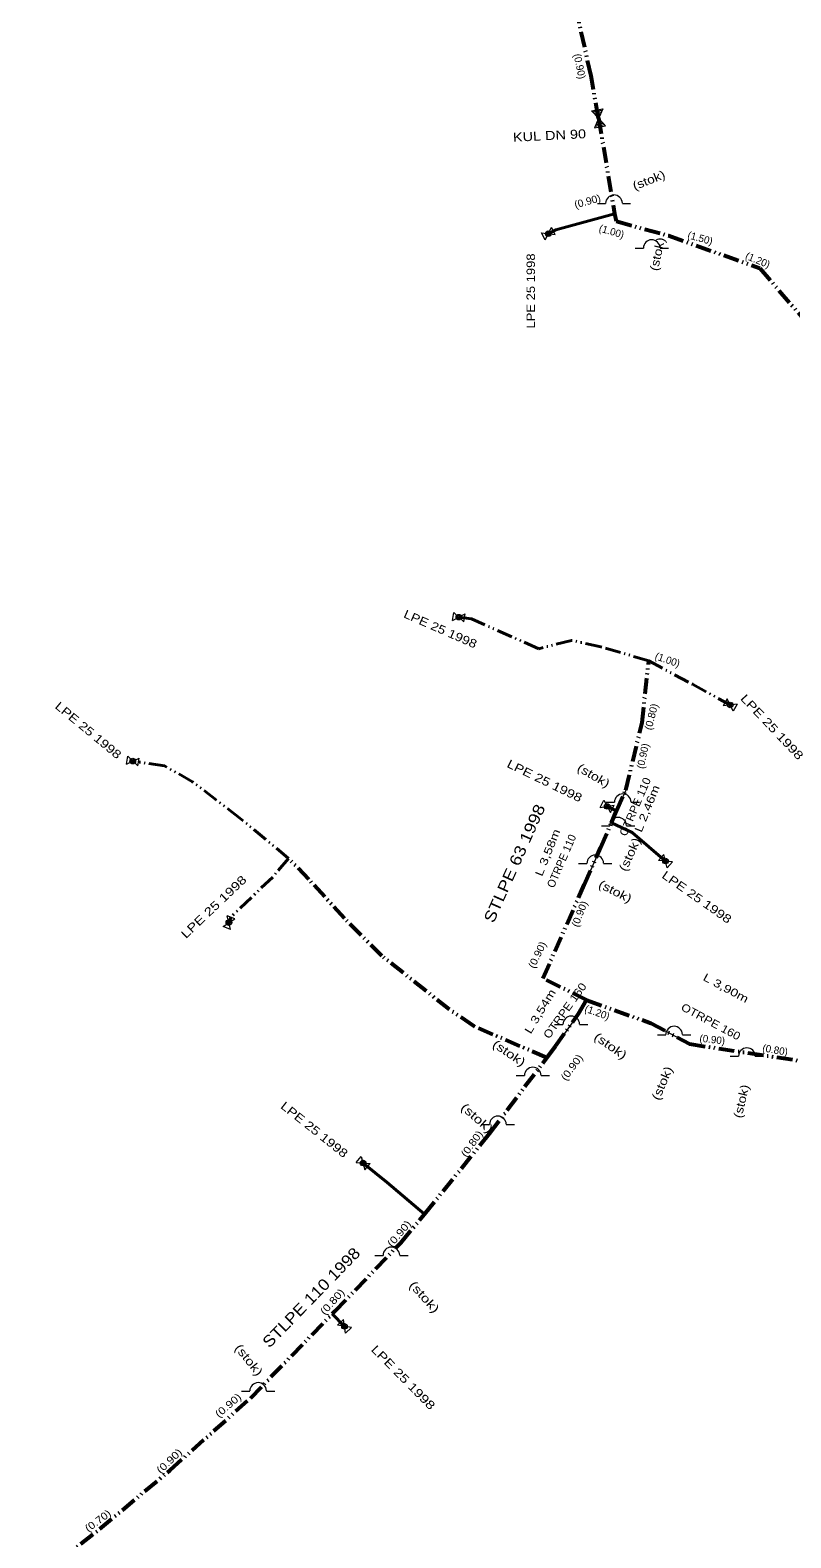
# Model space of a CAD drawing. Extents: x -648036 to -642998, y -1161549 to -1158141.
# Drawn here: x -644468.6 to -644401.1, y -1160280.5 to -1160146.5 of the extents above; entities that cross this region are included whole.
import ezdxf
from ezdxf.enums import TextEntityAlignment as Align

# ---------------------------------------------------------------- set-up
doc = ezdxf.new("R2010")
doc.units = 0
doc.header["$LTSCALE"] = 0.28
doc.linetypes.add('DASH_DOUBLE_DOT', pattern=[9.2, 5, -1.2, 0.3, -1.2, 0.3, -1.2])
for name, color, linetype, lineweight in [('12', 7, 'DASH_DOUBLE_DOT', 40), ('14', 7, 'Continuous', 13), ('15', 7, 'Continuous', 13), ('19', 7, 'Continuous', 13), ('8', 7, 'Continuous', 53)]:
    doc.layers.add(name, color=color, linetype=linetype, lineweight=lineweight)
for name, color, linetype in [('20', 7, 'Continuous'), ('22', 7, 'Continuous'), ('24', 7, 'Continuous'), ('27', 7, 'Continuous'), ('28', 7, 'Continuous'), ('35', 7, 'Continuous')]:
    doc.layers.add(name, color=color, linetype=linetype)

msp = doc.modelspace()

# ---------------------------------------------------------------- linework, layer by layer
at = {"layer": '12'}
msp.add_line((-644416.56, -1160215.89), (-644417.4, -1160215.48), dxfattribs=at)
at = {"layer": '12', "linetype": 'Continuous'}
msp.add_line((-644441.81, -1160260.58), (-644440.72, -1160261.68), dxfattribs=at)
for points in [[(-644416.74, -1160162.85), (-644421.97, -1160164.26), (-644422.63, -1160164.6)], [(-644417.02, -1160216.95), (-644415.19, -1160217.81), (-644412.22, -1160220.34)], [(-644433.61, -1160251.71), (-644436.92, -1160248.89), (-644439.07, -1160247.17)]]:
    msp.add_lwpolyline(points, dxfattribs=at)
at = {"layer": '12'}
for points in [[(-644413.71, -1160202.54), (-644417.97, -1160201.31), (-644420.56, -1160200.73), (-644423.48, -1160201.47), (-644429.44, -1160198.83), (-644430.57, -1160198.67)], [(-644413.71, -1160202.54), (-644409.84, -1160204.63), (-644406.48, -1160206.47)], [(-644445.69, -1160220.1), (-644450, -1160216.52), (-644454.21, -1160213.29), (-644456.69, -1160211.89), (-644459.51, -1160211.46)], [(-644445.69, -1160220.1), (-644447.09, -1160221.76), (-644450.78, -1160225.29), (-644450.98, -1160225.81)]]:
    msp.add_lwpolyline(points, dxfattribs=at)
at = {"layer": '14'}
for p, q in [((-644415.75, -1160214.04), (-644416.74, -1160216.3)), ((-644417.99, -1160219.17), (-644419.43, -1160222.45)), ((-644419.95, -1160233.91), (-644422, -1160236.8)), ((-644413.52, -1160234.74), (-644410.08, -1160236.59))]:
    msp.add_line(p, q, dxfattribs=at)
at = {"layer": '15'}
for p, q in [((-644417.865, -1160153.659), (-644418.691, -1160153.803)), ((-644417.932, -1160153.811), (-644418.576, -1160153.925)), ((-644417.989, -1160153.941), (-644418.478, -1160154.026)), ((-644418.038, -1160154.052), (-644418.394, -1160154.115)), ((-644418.102, -1160154.198), (-644418.285, -1160154.229)), ((-644417.624, -1160154.923), (-644418.488, -1160155.074)), ((-644417.734, -1160154.808), (-644418.425, -1160154.929)), ((-644417.836, -1160154.701), (-644418.365, -1160154.792)), ((-644417.949, -1160154.581), (-644418.298, -1160154.643)), ((-644418.062, -1160154.463), (-644418.232, -1160154.493)), ((-644418.275, -1160161.905), (-644417.54, -1160161.904)), ((-644416.054, -1160161.904), (-644415.32, -1160161.905)), ((-644423.241, -1160164.514), (-644422.02, -1160164.686)), ((-644422.915, -1160165.147), (-644423.241, -1160164.514)), ((-644422.915, -1160165.147), (-644422.345, -1160164.053)), ((-644422.02, -1160164.686), (-644422.345, -1160164.053)), ((-644414.925, -1160165.885), (-644414.19, -1160165.884)), ((-644412.704, -1160165.884), (-644411.97, -1160165.885)), ((-644431.119, -1160198.952), (-644431.019, -1160198.247)), ((-644431.119, -1160198.952), (-644430.021, -1160198.388)), ((-644431.019, -1160198.247), (-644430.122, -1160199.093)), ((-644430.122, -1160199.093), (-644430.021, -1160198.388)), ((-644406.75, -1160205.916), (-644407.093, -1160206.54)), ((-644405.867, -1160206.4), (-644407.093, -1160206.54)), ((-644406.209, -1160207.024), (-644406.75, -1160205.916)), ((-644405.867, -1160206.4), (-644406.209, -1160207.024)), ((-644460.062, -1160211.736), (-644459.955, -1160211.032)), ((-644460.062, -1160211.736), (-644458.958, -1160211.184)), ((-644459.955, -1160211.032), (-644459.066, -1160211.888)), ((-644459.066, -1160211.888), (-644458.958, -1160211.184)), ((-644418.009, -1160215.579), (-644417.697, -1160214.939)), ((-644418.009, -1160215.579), (-644416.791, -1160215.381)), ((-644417.697, -1160214.939), (-644417.104, -1160216.021)), ((-644417.495, -1160215.115), (-644416.76, -1160215.114)), ((-644417.104, -1160216.021), (-644416.791, -1160215.381)), ((-644415.274, -1160215.114), (-644414.54, -1160215.115)), ((-644417.905, -1160217.205), (-644417.17, -1160217.204)), ((-644415.684, -1160217.204), (-644414.95, -1160217.205)), ((-644412.372, -1160219.743), (-644412.835, -1160220.284)), ((-644412.067, -1160220.938), (-644412.372, -1160219.743)), ((-644419.935, -1160220.555), (-644419.2, -1160220.554)), ((-644417.714, -1160220.554), (-644416.98, -1160220.555)), ((-644411.605, -1160220.396), (-644412.835, -1160220.284)), ((-644411.605, -1160220.396), (-644412.067, -1160220.938)), ((-644450.467, -1160225.468), (-644451.131, -1160225.212)), ((-644450.829, -1160226.408), (-644451.131, -1160225.212)), ((-644451.493, -1160226.153), (-644450.467, -1160225.468)), ((-644450.829, -1160226.408), (-644451.493, -1160226.153)), ((-644422.065, -1160234.855), (-644421.33, -1160234.854)), ((-644419.844, -1160234.854), (-644419.11, -1160234.855)), ((-644412.935, -1160235.765), (-644412.2, -1160235.764)), ((-644410.714, -1160235.764), (-644409.98, -1160235.765)), ((-644406.475, -1160237.685), (-644405.74, -1160237.684)), ((-644404.254, -1160237.684), (-644403.52, -1160237.685)), ((-644425.485, -1160239.405), (-644424.75, -1160239.404)), ((-644423.264, -1160239.404), (-644422.53, -1160239.405)), ((-644428.575, -1160243.745), (-644427.84, -1160243.744)), ((-644426.354, -1160243.744), (-644425.62, -1160243.745)), ((-644439.686, -1160247.133), (-644439.241, -1160246.577)), ((-644439.241, -1160246.577), (-644438.9, -1160247.762)), ((-644439.686, -1160247.133), (-644438.454, -1160247.207)), ((-644438.9, -1160247.762), (-644438.454, -1160247.207)), ((-644438.035, -1160255.385), (-644437.3, -1160255.384)), ((-644435.814, -1160255.384), (-644435.08, -1160255.385)), ((-644440.821, -1160261.072), (-644441.328, -1160261.573)), ((-644440.618, -1160262.289), (-644440.821, -1160261.072)), ((-644440.112, -1160261.787), (-644441.328, -1160261.573)), ((-644440.112, -1160261.787), (-644440.618, -1160262.289)), ((-644449.865, -1160267.425), (-644449.13, -1160267.424)), ((-644447.644, -1160267.424), (-644446.91, -1160267.425))]:
    msp.add_line(p, q, dxfattribs=at)
msp.add_lwpolyline([(-644418.17, -1160154.35), (-644418.804, -1160153.684), (-644417.799, -1160153.51), (-644418.541, -1160155.191), (-644417.536, -1160155.016)], close=True, dxfattribs=at)
for centre in [(-644416.7974, -1160161.9046), (-644413.4474, -1160165.8846), (-644416.0174, -1160215.1146), (-644416.4274, -1160217.2046), (-644418.4574, -1160220.5546), (-644420.5874, -1160234.8546), (-644411.4574, -1160235.7646), (-644404.9974, -1160237.6846), (-644424.0074, -1160239.4046), (-644427.0974, -1160243.7446), (-644436.5574, -1160255.3846), (-644448.3874, -1160267.4246)]:
    msp.add_arc(centre, 0.7431, 1.2748, 179.83951, dxfattribs=at)
at = {"layer": '19'}
for centre, radius in [((-644422.63, -1160164.6), 0.25), ((-644422.63, -1160164.6), 0.17), ((-644422.63, -1160164.6), 0.09), ((-644430.57, -1160198.67), 0.25), ((-644430.57, -1160198.67), 0.17), ((-644430.57, -1160198.67), 0.09), ((-644406.48, -1160206.47), 0.25), ((-644406.48, -1160206.47), 0.17), ((-644406.48, -1160206.47), 0.09), ((-644459.51, -1160211.46), 0.25), ((-644459.51, -1160211.46), 0.17), ((-644459.51, -1160211.46), 0.09), ((-644417.4, -1160215.48), 0.25), ((-644417.4, -1160215.48), 0.17), ((-644417.4, -1160215.48), 0.09), ((-644412.22, -1160220.34), 0.25), ((-644412.22, -1160220.34), 0.17), ((-644412.22, -1160220.34), 0.09), ((-644450.98, -1160225.81), 0.25), ((-644450.98, -1160225.81), 0.17), ((-644450.98, -1160225.81), 0.09), ((-644439.07, -1160247.17), 0.25), ((-644439.07, -1160247.17), 0.17), ((-644439.07, -1160247.17), 0.09), ((-644440.72, -1160261.68), 0.25), ((-644440.72, -1160261.68), 0.17), ((-644440.72, -1160261.68), 0.09)]:
    msp.add_circle(centre, radius, dxfattribs=at)
at = {"layer": '8', "linetype": 'DASH_DOUBLE_DOT'}
msp.add_line((-644418.17, -1160154.35), (-644416.74, -1160162.85), dxfattribs=at)
for points in [[(-644418.17, -1160154.35), (-644418.83, -1160150.57), (-644421.18, -1160140.06)], [(-644416.74, -1160162.85), (-644416.6, -1160163.5), (-644411.96, -1160164.76), (-644403.86, -1160167.66), (-644399.13, -1160173.16)], [(-644416.56, -1160215.89), (-644415.75, -1160214.04), (-644414.31, -1160208.07), (-644413.71, -1160202.54)], [(-644417.02, -1160216.95), (-644416.74, -1160216.3), (-644416.56, -1160215.89)], [(-644419.21, -1160232.69), (-644423.1, -1160230.76), (-644419.43, -1160222.45), (-644417.99, -1160219.17), (-644417.02, -1160216.95)], [(-644422.76, -1160237.81), (-644429.25, -1160235.01), (-644431.4, -1160233.53), (-644437.4, -1160228.76), (-644440.72, -1160225.45), (-644443.87, -1160221.98), (-644445.69, -1160220.1)], [(-644422.76, -1160237.81), (-644422, -1160236.8), (-644419.95, -1160233.91), (-644419.21, -1160232.69)], [(-644419.21, -1160232.69), (-644413.52, -1160234.74), (-644410.08, -1160236.59), (-644399.79, -1160238.16), (-644398.39, -1160238.07), (-644386.73, -1160238.52), (-644382.19, -1160239.01), (-644376.02, -1160240.58), (-644372.99, -1160242.28)], [(-644433.61, -1160251.71), (-644427.84, -1160244.54), (-644422.76, -1160237.81)], [(-644441.81, -1160260.58), (-644441.58, -1160260.34), (-644435.72, -1160254.25), (-644433.61, -1160251.71)], [(-644468.62, -1160284.42), (-644468.24, -1160284.21), (-644462.44, -1160279.67), (-644456.19, -1160274.45), (-644449.06, -1160268.05), (-644441.81, -1160260.58)]]:
    msp.add_lwpolyline(points, dxfattribs=at)

# ---------------------------------------------------------------- texts
at = {"layer": '20'}
for s, rotation, width, p in [('STLPE 63 1998', 65.89, 1.2, (-644425.1734, -1160220.7472)), ('STLPE 110 1998', 45.837, 1.15, (-644443.3097, -1160259.4609))]:
    msp.add_text(s, height=1, rotation=rotation, dxfattribs=dict(at, width=width)).set_placement(p, align=Align.CENTER)
at = {"layer": '22'}
for rotation, width, p in [(89.954, 1.15, (-644423.8103, -1160169.6908)), (336.326, 1.2, (-644432.3546, -1160200.0603)), (320.283, 1.25, (-644463.6996, -1160209.0103)), (313.408, 1.3, (-644403.0391, -1160208.6823)), (334.034, 1.25, (-644423.1147, -1160213.5438)), (324.867, 1.25, (-644409.6583, -1160223.8533)), (43.545, 1.3, (-644452.0678, -1160224.6797)), (321.429, 1.25, (-644443.6293, -1160244.4922)), (314.554, 1.3, (-644435.7701, -1160266.4814))]:
    msp.add_text('LPE 25 1998', height=0.75, rotation=rotation, dxfattribs=dict(at, width=width)).set_placement(p, align=Align.CENTER)
at = {"layer": '24'}
for s, rotation, width, p in [('OTRPE 110 ', 66.463, 1.1, (-644414.544, -1160215.5188)), ('L 2,46m', 68.182, 1.3, (-644413.5371, -1160215.8076)), ('L 3,58m', 68.182, 1.3, (-644422.3642, -1160219.7131)), ('L 3,90m', 331.743, 1.3, (-644407.0267, -1160231.9279)), ('L 3,54m', 59.015, 1.3, (-644423.0597, -1160233.8732)), ('OTRPE 160', 54.431, 1.15, (-644420.8701, -1160233.8341)), ('OTRPE 160', 331.743, 1.15, (-644408.3627, -1160234.9139))]:
    msp.add_text(s, height=0.7, rotation=rotation, dxfattribs=dict(at, width=width)).set_placement(p, align=Align.CENTER)
msp.add_text('OTRPE 110', height=0.7, rotation=66.463, dxfattribs=at).set_placement((-644421.1328, -1160220.4773), align=Align.CENTER)
at = {"layer": '27'}
for s, rotation, p in [('(0.90)', 281.895, (-644420.1574, -1160149.7945)), ('(1.00)', 343.775, (-644417.0993, -1160164.7101)), ('(1.50)', 344.348, (-644409.2312, -1160165.302)), ('(1.20)', 337.472, (-644404.157, -1160167.2463)), ('(1.00)', 340.91, (-644412.1503, -1160202.7627)), ('(0.90)', 77.922, (-644413.9168, -1160211.074)), ('(1.20)', 340.337, (-644418.3954, -1160234.0931)), ('(0.90)', 353.515, (-644408.1072, -1160236.5123)), ('(0.80)', 350.077, (-644402.544, -1160237.4389))]:
    msp.add_text(s, height=0.65, rotation=rotation, dxfattribs=at).set_placement(p, align=Align.CENTER)
for s, rotation, width, p in [('(0.90)', 15.47, 1.05, (-644419.0637, -1160162.0335)), ('(0.80)', 75.63, 1.05, (-644413.1697, -1160207.5982)), ('(0.90)', 68.755, 1.05, (-644419.5522, -1160225.1493)), ('(0.90)', 64.171, 1.1, (-644423.317, -1160228.8121)), ('(0.90)', 53.858, 1.15, (-644420.282, -1160238.8627)), ('(0.80)', 54.431, 1.15, (-644429.1553, -1160245.64)), ('(0.90)', 49.847, 1.2, (-644435.6205, -1160253.6501)), ('(0.80)', 48.128, 1.2, (-644441.5672, -1160259.7044)), ('(0.90)', 40.68, 1.2, (-644450.8373, -1160268.9459)), ('(0.90)', 43.545, 1.2, (-644456.0519, -1160273.8788)), ('(0.70)', 36.669, 1.15, (-644462.4161, -1160279.2101))]:
    msp.add_text(s, height=0.65, rotation=rotation, dxfattribs=dict(at, width=width)).set_placement(p, align=Align.CENTER)
at = {"layer": '28'}
for rotation, width, p in [(21.772, 1.2, (-644413.5601, -1160160.1921)), (77.349, 1.2, (-644412.581, -1160166.4896)), (329.451, 1.25, (-644418.7976, -1160213.0638)), (65.317, 1.25, (-644415.0592, -1160219.9061)), (332.888, 1.25, (-644416.8544, -1160223.3612)), (324.867, 1.3, (-644417.3193, -1160237.063)), (325.44, 1.3, (-644426.3202, -1160237.7067)), (67.036, 1.25, (-644412.1734, -1160240.2243)), (76.776, 1.2, (-644405.1284, -1160241.7668)), (318.565, 1.35, (-644429.2062, -1160243.4531)), (312.262, 1.35, (-644433.9067, -1160259.3168)), (308.824, 1.3, (-644449.5018, -1160264.8954))]:
    msp.add_text('(stok)', height=0.75, rotation=rotation, dxfattribs=dict(at, width=width)).set_placement(p, align=Align.CENTER)
at = {"layer": '35', "width": 1.2}
msp.add_text('KUL DN 90', height=0.8, rotation=2.865, dxfattribs=at).set_placement((-644422.503, -1160156.2747), align=Align.CENTER)

doc.saveas('drawing.dxf')
